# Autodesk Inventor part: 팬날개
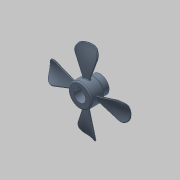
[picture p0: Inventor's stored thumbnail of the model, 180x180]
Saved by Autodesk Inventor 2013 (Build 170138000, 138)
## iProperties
Company: 한국ATC센터
Created: 2016-06
Part Number: 팬날개
Document SubType Name: Modeling
Designer: mdu
Density: 1.493 g/cm^3
Material: PC/ABS 플라스틱
Mass: 34.8713 g
Surface Area: 136.353 cm^2
Volume: 23.3566 cm^3
Author: mdu
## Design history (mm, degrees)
sketch "스케치1"
  geometry: L1 (-15, 0)-(15, 0); L2 (-15, 0)-(-15, 17); L3 (-15, 17)-(5, 17); L4 (5, 17)-(5, 13); L5 (5, 13)-(15, 13); L6 (15, 13)-(15, 0); 2 further points
  constraints: 12 end point, 3 parallel, 2 perpendicular, 1 coincident, 1 horizontal, 1 midpoint
  dimensions: "d0" = 30 distance of L1.start L1.end; "d8" = 34 diameter of L3 L1; "d10" = 26 diameter of L5 L1; "d32" = 20 distance of L2.end L3.end
revolve "회전1" sketch "스케치1" stored, may be unused: angle "d11" = 90 deg
node "작업 평면2"
sketch "스케치7"
  geometry: L1 (-15, 17)-(5, 17) reference; L2 (-15, -17)-(5, -17) reference; L3 (-5, 17)-(-5, -17); A1 r 35 centre (-38.719, -8.43) between (-4, -4) and (-6, 4); 1 further point
  constraints: 2 end point, 2 midpoint, 2 point on circle, 1 centre point
  dimensions: "d36" = 35 radius of A1; "d37" = 13 distance from line of A1.start L2; "d38" = 13 distance from line of A1.end L1; "d45" = 1 distance from line of A1.end L3; "d46" = 1 distance from line of A1.start L3
sketch "3D 스케치1"
  geometry: L1 through (0, 0) direction (1, 0) reference; L2 through (0, 0) direction (1, 0) reference; 13 other entities
  constraints: 2 collinear
  node "투영 원본 위치 스케치7"
sketch "스케치8"
  geometry: L1 (-15, 17)-(5, 17) reference; L2 (-15, -17)-(5, -17) reference; L3 (-5, 17)-(-5, -17); A1 r 30 centre (-28.74, -3.591) between (-3, -19) and (-9, 19); 1 further point
  constraints: 2 end point, 2 midpoint, 2 point on circle, 1 centre point
  dimensions: "d43" = 30 radius of A1; "d47" = 4 distance from line of A1.end L3; "d48" = 2 distance from line of A1.start L3; "d58" = 2 distance from line of A1.end L1; "d59" = 2 distance from line of A1.start L2
sketch "3D 스케치2"
sketch "3D 스케치3"
feature "경계 패치1" sketch "3D 스케치2", "3D 스케치3" dims "d50" = 0
feature "연장1" dims "d55" = 2
feature "두껍게 하기1" dims "d51" = 2, "d52" = 2
sketch "스케치9"
  geometry: C1 r 59 at (0, 0); 1 further point
  constraints: 1 centre point, 1 coincident
  dimensions: "d60" = 118 diameter of C1
extrude "돌출2" sketch "스케치9" distance "d62" = 200; taper "d63" = 0 deg
fillet "모깎기6" dims "d64" = 10
fillet "모깎기7" dims "d66" = 0.8
fillet "모깎기8" dims "d67" = 0.8
sketch "스케치2"
  geometry: L1 (-2.5, 8.124)-(-2.5, 10.8); L2 (-2.5, 10.8)-(2.5, 10.8); L3 (2.5, 10.8)-(2.5, 8.124); A1 r 8.5 centre (0, 0) between (-2.5, 8.124) and (2.5, 8.124); 1 further point
  constraints: 6 end point, 2 parallel, 2 point on circle, 1 centre point, 1 coincident, 1 horizontal, 1 vertical
  dimensions: "d12" = 17 diameter of A1; "d13" = 5 distance of L1.end L2.end; "d14" = 19.3 dimension on A1 L2 (computed from d12)
extrude "돌출1" cut sketch "스케치2" stored distance "d15" = 10; taper "d16" = 0 deg
chamfer "모따기1" distance "d17" = 1; stored, may be unused: second distance "d18" = 2, angle "d19" = 45 deg
node "작업 평면1"
sketch "스케치3"
  geometry: L1 (5, -13)-(5, 13) reference; 3 further points
  constraints: 1 horizontal alignment, 1 midpoint
  dimensions: "d20" = 5 distance from line of L1 point (0, 0)
hole "구멍1" sketch "스케치3" at (0, 0) diameter "d21" = 3.242; stored, may be unused: countersink angle "d25" = 90 deg, drill point angle "d27" = 118 deg; dims "d22" = 6, "d23" = 4, "d24" = 2, "d26" = 8
fillet "모깎기9" dims "d77" = 2
fillet "모깎기10" dims "d78" = 2
fillet "모깎기11" dims "d79" = 2
node "솔리드1"
pattern_circular "원형 패턴1" dims "d69" = 360 deg
pattern_circular "원형 패턴2" dims angle "d72" = 360 deg
pattern_circular "원형 패턴3" dims angle "d75" = 360 deg
node "투영 원본 위치 스케치8"
node "곡면1"
node "곡면2"
node "곡면3"
node "곡면4"
feature "경계 패치2"
feature "경계 패치3"
feature "경계 패치4"
